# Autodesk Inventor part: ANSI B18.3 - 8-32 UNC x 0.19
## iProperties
IsCustomPart: 0
Created: 2008-02
Part Number: ANSI B18.3 - 8-32 UNC x 0.19
Material: Steel, Mild
Description: Hexagon Socket Set Screw - Flat Point
Document SubType Name: Modeling
Standard: ANSI B18.3
Standard Revision: 2003
Standards Organization: ANSI
Language: en-US
Size Designation: 8-32 UNC x 0.19
Categories: <MemberInstance><Categories><Category DisplayName="Fasteners" InternalName="e4da775c-781d-43d5-af7c-5136215cf5a6" Mnemonic="FSTN"><Category DisplayName="Bolts"
Density: 7.86 g/cm^3
Mass: 0.426476 g
Surface Area: 0.989445 cm^2
Volume: 0.054259 cm^3
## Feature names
1. Body [Revolution]
2. Chamfer1
3. Slot [Extrusion]
4. Chamfer2
